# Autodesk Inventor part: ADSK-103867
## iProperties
Shininess: 0.0
Created: 2000-11
Part Number: ADSK-103867
Document SubType Name: Modeling
Stock Number: ADSK-103867
Density: 1 g/cm^3
Density: 0.0
Volumn: 0.0
Area: 0.0
PropertySet Name: Model Information
Control State: 0
Master: False
Checked Out: False
Author: gao
